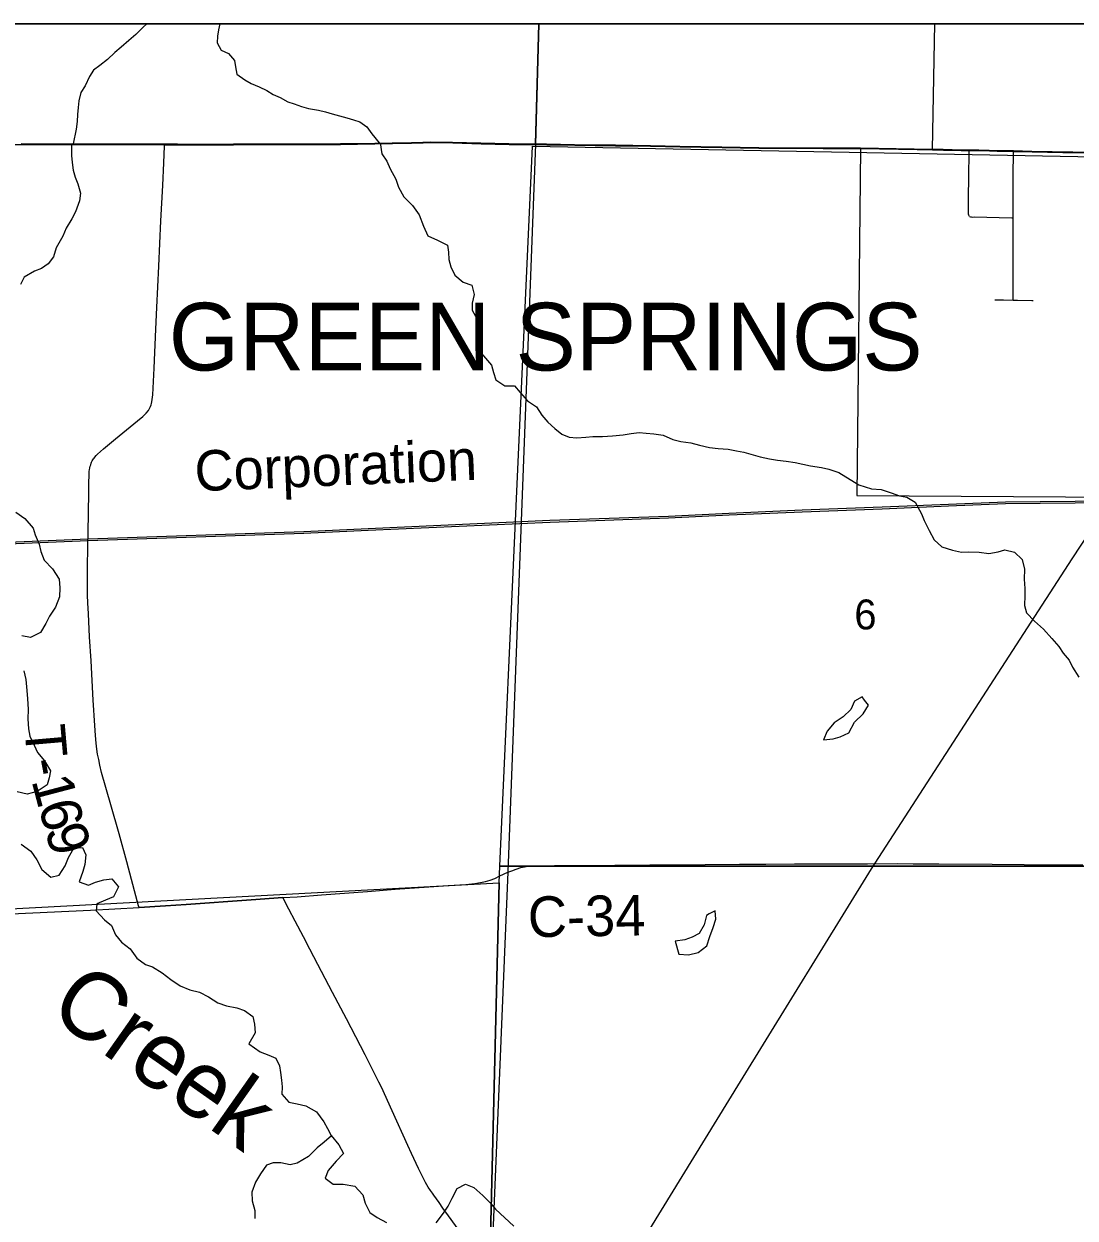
# Model space of a CAD drawing. Extents: x 0 to 34, y 0 to 22.
# Drawn here: x 6.439 to 7.175, y 20.064 to 20.9 of the extents above; entities that cross this region are included whole.
import ezdxf

# ---------------------------------------------------------------- set-up
doc = ezdxf.new("R2010")
doc.units = 0
for name, color, linetype in [('GM_X_City_Street', 7, 'Continuous'), ('GM_X_Corporation', 7, 'Continuous'), ('GM_X_Corporation_Text', 7, 'Continuous'), ('GM_X_County_Road', 7, 'Continuous'), ('GM_X_County_Road_Text', 7, 'Continuous'), ('GM_X_Minor_Lake', 7, 'Continuous'), ('GM_X_Minor_River', 7, 'Continuous'), ('GM_X_Minor_River_Text', 7, 'Continuous'), ('GM_X_Rail_Line', 7, 'Continuous'), ('GM_X_Rail_Line_Text', 7, 'Continuous'), ('GM_X_Section_Text', 7, 'Continuous'), ('GM_X_Township_Road', 7, 'Continuous'), ('GM_X_Township_Road_Text', 7, 'Continuous'), ('SH_Data', 7, 'Continuous')]:
    doc.layers.add(name, color=color, linetype=linetype)

msp = doc.modelspace()

# ---------------------------------------------------------------- linework, layer by layer
at = {"layer": 'GM_X_City_Street'}
for points in [[(7.10112, 20.76525), (7.1008, 20.76573), (7.10065, 20.76622), (7.10053, 20.76682), (7.10052, 20.76744), (7.10042, 20.76931), (7.10045, 20.77259), (7.10041, 20.78121), (7.10059, 20.78997), (7.10077, 20.79874), (7.10083, 20.8043), (7.10087, 20.81065), (7.10088, 20.81138)], [(7.13164, 20.70675), (7.13164, 20.70778), (7.13167, 20.71185), (7.13163, 20.73614), (7.13178, 20.74982), (7.13172, 20.76426), (7.13171, 20.76758), (7.13169, 20.78127), (7.13179, 20.79403), (7.13203, 20.81001), (7.13204, 20.81081)], [(7.10112, 20.76525), (7.1018, 20.76499), (7.10245, 20.7649), (7.10336, 20.76486), (7.10441, 20.7649), (7.13072, 20.76428), (7.13172, 20.76426)], [(7.11889, 20.70698), (7.12482, 20.70688), (7.13164, 20.70675), (7.13473, 20.70669), (7.14467, 20.7065), (7.1456, 20.7065)]]:
    msp.add_lwpolyline(points, dxfattribs=at)
at = {"layer": 'GM_X_Corporation'}
for points in [[(8.9, 20.9), (2.1, 20.9)], [(6.43728, 20.81597), (6.455, 20.81586), (6.49788, 20.8159), (6.51124, 20.8159), (6.53738, 20.81573), (6.54665, 20.81576), (6.55659, 20.81567), (6.58581, 20.81575), (6.60943, 20.81589), (6.6231, 20.81581), (6.64388, 20.81578), (6.66067, 20.81598), (6.67247, 20.81615), (6.69702, 20.81654), (6.7104, 20.81681), (6.7184, 20.81707), (6.72404, 20.81719), (6.73918, 20.81697), (6.75907, 20.81646), (6.77865, 20.816), (6.79733, 20.81582), (6.79968, 20.9), (3.80131, 20.9)], [(8.9, 20.9), (6.79968, 20.9), (6.79733, 20.81582), (6.80505, 20.81575), (6.82462, 20.81548), (6.8532, 20.81506), (6.87775, 20.81462), (6.89835, 20.81423), (6.92778, 20.81367), (6.95357, 20.81337), (6.99856, 20.81315), (7.02492, 20.81305), (7.07501, 20.81217), (7.08275, 20.81203), (7.09521, 20.81169), (7.10077, 20.81165), (7.10763, 20.8116), (7.1149, 20.81141), (7.12034, 20.81127), (7.1296, 20.81114), (7.13193, 20.81108), (7.14484, 20.81082), (7.17346, 20.81025), (7.19996, 20.80975)], [(7.61604, 20.9), (7.07654, 20.9), (7.07501, 20.81217), (7.02492, 20.81305), (7.02214, 20.57001), (7.2781, 20.56846)], [(7.19996, 20.80975), (7.17346, 20.81025), (7.14484, 20.81082), (7.13193, 20.81108), (7.1296, 20.81114), (7.12034, 20.81127), (7.1149, 20.81141), (7.10763, 20.8116), (7.10077, 20.81165), (7.09521, 20.81169), (7.08275, 20.81203), (7.07501, 20.81217), (7.02492, 20.81305), (6.99856, 20.81315), (6.95357, 20.81337), (6.92778, 20.81367), (6.89835, 20.81423), (6.87775, 20.81462), (6.8532, 20.81506), (6.82462, 20.81548), (6.80505, 20.81575), (6.79733, 20.81582), (6.77865, 20.816), (6.75907, 20.81646), (6.73918, 20.81697), (6.72404, 20.81719), (6.7184, 20.81707), (6.7104, 20.81681), (6.69702, 20.81654), (6.67247, 20.81615), (6.66067, 20.81598), (6.64388, 20.81578), (6.6231, 20.81581), (6.60943, 20.81589), (6.58581, 20.81575), (6.55659, 20.81567), (6.54665, 20.81576), (6.53738, 20.81573), (6.51124, 20.8159), (6.49788, 20.8159), (6.455, 20.81586), (6.43728, 20.81597)], [(6.43728, 20.81597), (6.455, 20.81586), (6.49788, 20.8159), (6.51124, 20.8159), (6.53738, 20.81573), (6.54665, 20.81576), (6.55659, 20.81567), (6.58581, 20.81575), (6.60943, 20.81589), (6.6231, 20.81581), (6.64388, 20.81578), (6.66067, 20.81598), (6.67247, 20.81615), (6.69702, 20.81654), (6.7104, 20.81681), (6.7184, 20.81707), (6.72404, 20.81719), (6.73918, 20.81697), (6.75907, 20.81646), (6.77865, 20.816), (6.79733, 20.81582), (6.80505, 20.81575), (6.82462, 20.81548), (6.8532, 20.81506), (6.87775, 20.81462), (6.89835, 20.81423), (6.92778, 20.81367), (6.95357, 20.81337), (6.99856, 20.81315), (7.02492, 20.81305), (7.07501, 20.81217), (7.08275, 20.81203), (7.09521, 20.81169), (7.10077, 20.81165), (7.10763, 20.8116), (7.1149, 20.81141), (7.12034, 20.81127), (7.1296, 20.81114), (7.13193, 20.81108), (7.14484, 20.81082), (7.17346, 20.81025), (7.19996, 20.80975)], [(6.43728, 20.81597), (6.455, 20.81586), (6.49788, 20.8159), (6.51124, 20.8159), (6.53738, 20.81573), (6.54665, 20.81576), (6.55659, 20.81567), (6.58581, 20.81575), (6.60943, 20.81589), (6.6231, 20.81581), (6.64388, 20.81578), (6.66067, 20.81598), (6.67247, 20.81615), (6.69702, 20.81654), (6.7104, 20.81681), (6.7184, 20.81707), (6.72404, 20.81719), (6.73918, 20.81697), (6.75907, 20.81646), (6.77865, 20.816), (6.79733, 20.81582), (6.77787, 20.30669), (6.76561, 20.00895)], [(7.19996, 20.80975), (7.17346, 20.81025), (7.14484, 20.81082), (7.13193, 20.81108), (7.1296, 20.81114), (7.12034, 20.81127), (7.1149, 20.81141), (7.10763, 20.8116), (7.10077, 20.81165), (7.09521, 20.81169), (7.08275, 20.81203), (7.07501, 20.81217), (7.02492, 20.81305), (6.99856, 20.81315), (6.95357, 20.81337), (6.92778, 20.81367), (6.89835, 20.81423), (6.87775, 20.81462), (6.8532, 20.81506), (6.82462, 20.81548), (6.80505, 20.81575), (6.79733, 20.81582), (6.77787, 20.30669), (6.76561, 20.00895)]]:
    msp.add_lwpolyline(points, dxfattribs=at)
for points in [[(6.7951, 20.81454), (7.27539, 20.80543), (7.27412, 20.31079), (6.77234, 20.31066)], [(6.77234, 20.31066), (7.27412, 20.31079), (7.26913, 19.80885), (6.75975, 19.80499), (6.77189, 20.29891)], [(6.25404, 20.2716), (6.77189, 20.29891), (6.75975, 19.80499), (6.75951, 19.79722), (6.2587, 19.76677)]]:
    msp.add_lwpolyline(points, close=True, dxfattribs=at)
at = {"layer": 'GM_X_County_Road'}
for p, q in [((6.79744, 20.81554), (6.7998, 20.9)), ((7.02503, 20.81278), (7.0646, 20.81208)), ((7.0646, 20.81208), (7.07512, 20.81189))]:
    msp.add_line(p, q, dxfattribs=at)
for points in [[(6.29547, 20.81566), (6.30376, 20.81554), (6.33453, 20.81553), (6.35442, 20.81556), (6.39389, 20.81563), (6.43739, 20.81569), (6.45511, 20.81558), (6.49799, 20.81562), (6.51135, 20.81562), (6.53749, 20.81545)], [(6.53749, 20.81545), (6.54676, 20.81548), (6.5567, 20.8154), (6.58592, 20.81547), (6.60954, 20.81562), (6.62321, 20.81553), (6.64399, 20.8155), (6.66078, 20.81571), (6.67258, 20.81587), (6.69713, 20.81627), (6.71051, 20.81653), (6.71852, 20.8168), (6.72415, 20.81691), (6.73929, 20.81669), (6.75918, 20.81618), (6.77876, 20.81572), (6.79744, 20.81554)], [(6.79744, 20.81554), (6.80517, 20.81547), (6.82473, 20.8152), (6.85331, 20.81479), (6.87786, 20.81434), (6.89846, 20.81395), (6.92789, 20.8134), (6.95368, 20.8131), (6.99867, 20.81288), (7.02503, 20.81278)], [(7.07512, 20.81189), (7.08286, 20.81175), (7.09532, 20.81141), (7.10088, 20.81138)], [(7.10088, 20.81138), (7.10774, 20.81133), (7.11501, 20.81113), (7.12045, 20.81099), (7.12971, 20.81087), (7.13204, 20.81081)], [(7.13204, 20.81081), (7.14495, 20.81055), (7.16654, 20.81011)], [(7.16654, 20.81011), (7.17357, 20.80997), (7.20007, 20.80947), (7.21463, 20.80912), (7.22592, 20.80892)], [(6.62038, 20.28865), (6.63048, 20.28928), (6.64752, 20.29065), (6.67976, 20.29296), (6.69898, 20.29448), (6.73619, 20.29709), (6.74859, 20.29794), (6.75475, 20.29855), (6.75872, 20.29915), (6.76232, 20.29996), (6.76556, 20.30095), (6.76873, 20.30215), (6.77239, 20.3038), (6.77798, 20.30641)], [(6.77798, 20.30641), (6.78065, 20.3075), (6.78363, 20.3085), (6.78702, 20.30964), (6.79078, 20.31044), (6.79417, 20.31081), (6.7967, 20.31094), (6.80092, 20.31099), (6.81057, 20.31122), (6.85284, 20.31139), (6.86744, 20.31148), (6.87739, 20.3116), (6.89199, 20.31165), (6.94016, 20.31201), (6.95849, 20.31214), (6.9787, 20.31231), (7.00108, 20.31231), (7.02964, 20.31239), (7.05075, 20.31243), (7.06164, 20.31238), (7.07966, 20.3122), (7.11696, 20.31197), (7.13934, 20.31183), (7.18036, 20.3116)], [(6.51975, 20.28164), (6.53833, 20.28293), (6.5528, 20.28394), (6.59829, 20.2872), (6.62038, 20.28865)], [(6.25408, 20.27027), (6.31869, 20.27283), (6.37801, 20.27524), (6.43018, 20.27742), (6.4857, 20.27993), (6.51975, 20.28164)]]:
    msp.add_lwpolyline(points, dxfattribs=at)
at = {"layer": 'GM_X_Minor_Lake'}
for points in [[(7.02768, 20.42688), (7.02603, 20.42913), (7.02071, 20.42613), (7.01803, 20.42027), (7.0127, 20.41518), (7.00644, 20.41104), (7.00148, 20.40519), (6.9988, 20.39914)], [(6.9988, 20.39914), (7.00562, 20.39986), (7.01054, 20.40116), (7.01661, 20.40397), (7.02063, 20.41134), (7.02671, 20.41737), (7.03034, 20.42323), (7.02768, 20.42688)], [(6.89508, 20.25827), (6.89767, 20.24915), (6.90429, 20.24873), (6.91111, 20.25021), (6.91719, 20.25492), (6.91931, 20.26154), (6.92161, 20.26779), (6.92354, 20.27365), (6.92301, 20.27954), (6.91894, 20.27727)], [(6.91894, 20.27727), (6.91693, 20.27616), (6.91538, 20.26953), (6.91175, 20.26348), (6.90701, 20.26104), (6.90189, 20.25918), (6.89508, 20.25827)]]:
    msp.add_lwpolyline(points, dxfattribs=at)
at = {"layer": 'GM_X_Minor_River'}
for points in [[(6.52522, 20.9), (6.52264, 20.8977), (6.51746, 20.89263), (6.51267, 20.88831), (6.50712, 20.88363), (6.50271, 20.88007), (6.49754, 20.87519), (6.49237, 20.87088), (6.48778, 20.8677), (6.48507, 20.86317), (6.48197, 20.85675), (6.47888, 20.85204), (6.47767, 20.84617), (6.47705, 20.84143), (6.47661, 20.8365), (6.47637, 20.83176), (6.47574, 20.82645), (6.47366, 20.81611)], [(6.57632, 20.9), (6.57534, 20.8958), (6.57472, 20.89144), (6.57448, 20.8867), (6.57727, 20.88155), (6.58236, 20.87921), (6.58648, 20.87443), (6.58718, 20.86986), (6.58827, 20.86492), (6.59372, 20.86087), (6.59824, 20.85836), (6.60391, 20.85602), (6.60919, 20.8533), (6.61371, 20.8506), (6.61842, 20.84846), (6.62389, 20.84536), (6.62823, 20.84399), (6.63353, 20.84222), (6.63844, 20.84084), (6.64525, 20.83963), (6.65036, 20.83844), (6.6549, 20.83706), (6.66, 20.83567), (6.6653, 20.83429), (6.66983, 20.83291), (6.67418, 20.83154), (6.67926, 20.82807), (6.68281, 20.82309), (6.68781, 20.81689)], [(6.47247, 20.81601), (6.47247, 20.8078), (6.47282, 20.80306), (6.47355, 20.79774), (6.47503, 20.7928), (6.47689, 20.78805), (6.47874, 20.78159), (6.47795, 20.7761), (6.47525, 20.76853), (6.47257, 20.76361), (6.46874, 20.757), (6.46625, 20.75152), (6.46165, 20.74339), (6.45972, 20.73695), (6.45609, 20.73205), (6.45134, 20.72885), (6.4466, 20.72698), (6.43938, 20.72267), (6.4367, 20.71775)], [(6.68845, 20.81678), (6.68959, 20.80913), (6.69315, 20.80399), (6.69558, 20.79866), (6.69951, 20.79124), (6.70136, 20.78573), (6.70511, 20.77907), (6.71112, 20.77297), (6.71582, 20.76649), (6.71898, 20.75851), (6.72197, 20.75166), (6.72857, 20.74859), (6.73574, 20.74513), (6.73647, 20.74038), (6.73662, 20.73507), (6.73792, 20.72995), (6.74072, 20.72424), (6.74675, 20.71927), (6.7526, 20.71715), (6.75445, 20.71069), (6.7529, 20.70463), (6.75287, 20.6997), (6.75642, 20.69342), (6.75941, 20.68714), (6.75804, 20.68052), (6.75629, 20.67332), (6.76099, 20.66779), (6.76644, 20.66112), (6.76792, 20.65618), (6.76959, 20.65105), (6.77581, 20.64684), (6.78262, 20.6468), (6.78657, 20.64203), (6.79164, 20.63631), (6.79805, 20.6321), (6.8018, 20.6262), (6.80593, 20.62124), (6.81083, 20.61685), (6.81572, 20.61303), (6.82082, 20.61091), (6.8263, 20.61031), (6.83255, 20.61084), (6.83748, 20.61119), (6.84429, 20.61134), (6.8513, 20.61186), (6.85869, 20.61257), (6.86418, 20.61349), (6.86986, 20.61421), (6.87478, 20.61361), (6.88008, 20.6132), (6.8867, 20.61221), (6.89349, 20.60932), (6.89897, 20.60777), (6.90597, 20.60697), (6.91202, 20.60523), (6.91901, 20.60367), (6.92525, 20.60287), (6.93225, 20.60245), (6.93792, 20.60127), (6.94302, 20.60029), (6.94794, 20.59893), (6.95455, 20.597), (6.96116, 20.59563), (6.96665, 20.59483), (6.9727, 20.59404), (6.97913, 20.59305), (6.98442, 20.59188), (6.9899, 20.59071), (6.99747, 20.58971), (7.00257, 20.58835), (7.00975, 20.58603), (7.0236, 20.57751)], [(7.0236, 20.57751), (7.03255, 20.57473), (7.03936, 20.57413), (7.04634, 20.572), (7.05219, 20.56988), (7.0573, 20.5689), (7.06314, 20.56526), (7.06763, 20.55727), (7.06931, 20.55252), (7.07286, 20.54549), (7.07642, 20.53902), (7.08169, 20.53406), (7.08924, 20.53174), (7.09547, 20.53037), (7.10077, 20.53072), (7.10796, 20.5303), (7.11457, 20.52951), (7.1212, 20.53061), (7.12594, 20.5319), (7.13274, 20.53035), (7.13801, 20.5252), (7.13967, 20.51855), (7.13944, 20.51154), (7.13978, 20.5049), (7.13994, 20.50015), (7.13971, 20.49295), (7.141, 20.48801), (7.14664, 20.4821), (7.15286, 20.47657), (7.15887, 20.46989), (7.16357, 20.46437), (7.16676, 20.45961), (7.17089, 20.45484), (7.17313, 20.4499), (7.17763, 20.44286)], [(6.43335, 20.55841), (6.43976, 20.55383), (6.44558, 20.54716), (6.44688, 20.54241), (6.44987, 20.53595), (6.45097, 20.53082), (6.45321, 20.52474), (6.45923, 20.51864), (6.46372, 20.51141), (6.46426, 20.50552), (6.46403, 20.49908), (6.46134, 20.49189), (6.45695, 20.48565), (6.45446, 20.48055), (6.45083, 20.47412), (6.44362, 20.47075), (6.43758, 20.47173)], [(6.43895, 20.44726), (6.44043, 20.44118), (6.44096, 20.43606), (6.44168, 20.42809), (6.4422, 20.42031), (6.44178, 20.41387), (6.44231, 20.40666), (6.44322, 20.40153), (6.44621, 20.39526), (6.44864, 20.39031), (6.45353, 20.38441), (6.45765, 20.37737), (6.45686, 20.37244), (6.45532, 20.36752), (6.4483, 20.36282), (6.44129, 20.36115), (6.43449, 20.36271)], [(6.4373, 20.32609), (6.44389, 20.32112), (6.44821, 20.31503), (6.45176, 20.30837), (6.45797, 20.30303), (6.46385, 20.30432), (6.46805, 20.31094), (6.47035, 20.3168), (6.47417, 20.32323), (6.48004, 20.32377), (6.48247, 20.31863), (6.48167, 20.31181), (6.48032, 20.30689), (6.47782, 20.29969), (6.48443, 20.29738), (6.48917, 20.29944), (6.49504, 20.30111), (6.50072, 20.30184), (6.50542, 20.29613), (6.50178, 20.28932), (6.49628, 20.28688), (6.49021, 20.28426), (6.48962, 20.27934), (6.49564, 20.27323), (6.50053, 20.26923), (6.50314, 20.26257), (6.50746, 20.25743), (6.51349, 20.25284), (6.51818, 20.24637), (6.52421, 20.24197), (6.52912, 20.24024), (6.5359, 20.23603), (6.54193, 20.23145), (6.54852, 20.22686), (6.55532, 20.22416), (6.56212, 20.22242), (6.56834, 20.21916), (6.57494, 20.21514), (6.58098, 20.21302), (6.58816, 20.21165), (6.59345, 20.20973), (6.59948, 20.20552), (6.60058, 20.20021), (6.60111, 20.19413), (6.59653, 20.18638), (6.60444, 20.18084), (6.61067, 20.17853), (6.61558, 20.17642), (6.618, 20.17109)], [(6.618, 20.17109), (6.61873, 20.16635), (6.61946, 20.16103), (6.61981, 20.15629), (6.61959, 20.15117), (6.62448, 20.14546), (6.63052, 20.14428), (6.63638, 20.14292), (6.64392, 20.13871), (6.64899, 20.13185), (6.65161, 20.1271), (6.65423, 20.12215), (6.65968, 20.11567), (6.66286, 20.10959), (6.65772, 20.10431), (6.6522, 20.0977), (6.65008, 20.0924), (6.65573, 20.0882), (6.66254, 20.08816), (6.67086, 20.08679), (6.67631, 20.08069), (6.67798, 20.07499), (6.68135, 20.06833), (6.68643, 20.06489), (6.69303, 20.06125)], [(6.65437, 20.12198), (6.64928, 20.11763), (6.64434, 20.11368), (6.63825, 20.10764), (6.63047, 20.10294), (6.62555, 20.10164), (6.61893, 20.10301), (6.61364, 20.10304), (6.6089, 20.10155), (6.6047, 20.0955), (6.60126, 20.08964), (6.59876, 20.08264), (6.59892, 20.07657), (6.60077, 20.06974), (6.60073, 20.06405)], [(6.72784, 20.06105), (6.7328, 20.06785), (6.73604, 20.07276), (6.73891, 20.07844), (6.74236, 20.08505), (6.74824, 20.08825), (6.75409, 20.08575), (6.76049, 20.08021), (6.76538, 20.07544), (6.76932, 20.07068), (6.78212, 20.05885)]]:
    msp.add_lwpolyline(points, dxfattribs=at)
at = {"layer": 'GM_X_Rail_Line'}
for points in [[(4.83086, 16.81428), (4.95348, 17.00356), (5.121, 17.25544), (5.31678, 17.55326), (5.45252, 17.7592), (5.58679, 17.98275), (5.74825, 18.23979), (5.90418, 18.49744), (6.02127, 18.68264), (6.13663, 18.87252), (6.2288, 19.01731), (6.34315, 19.20099), (6.38785, 19.27035), (6.55501, 19.53303), (6.71382, 19.79395), (6.76349, 19.87076), (6.84474, 20.00352), (6.94083, 20.16003), (7.03262, 20.3087), (7.17305, 20.5257), (7.19919, 20.56539)], [(6.26535, 20.53071), (6.48407, 20.5397), (6.63504, 20.54492), (6.68014, 20.54698), (6.80739, 20.55272), (6.89038, 20.55561), (6.93271, 20.55766), (6.98399, 20.55992), (7.03989, 20.56198), (7.08643, 20.56393), (7.12632, 20.56558), (7.1993, 20.56635), (7.30727, 20.56381), (7.45258, 20.56138), (7.51394, 20.56039)], [(6.2654, 20.52947), (6.48412, 20.53846), (6.63509, 20.54368), (6.6802, 20.54573), (6.80744, 20.55148), (6.89043, 20.55437), (6.93276, 20.55642), (6.98404, 20.55868), (7.03994, 20.56074), (7.08648, 20.56269), (7.12635, 20.56433), (7.1993, 20.56511)]]:
    msp.add_lwpolyline(points, dxfattribs=at)
at = {"layer": 'GM_X_Township_Road'}
for points in [[(6.51975, 20.28164), (6.51938, 20.28301), (6.5166, 20.29348), (6.51121, 20.31377), (6.50574, 20.33321), (6.49994, 20.35353), (6.49353, 20.37626), (6.49227, 20.38139), (6.49148, 20.38532), (6.49074, 20.38902), (6.49024, 20.39264), (6.48969, 20.3967), (6.48917, 20.40201), (6.48869, 20.40909), (6.48762, 20.42677), (6.48617, 20.45438), (6.48514, 20.47113), (6.48423, 20.48726), (6.4838, 20.49503), (6.48369, 20.5003), (6.48364, 20.50334), (6.48361, 20.50683), (6.48368, 20.52019), (6.48388, 20.5336), (6.48405, 20.54532), (6.48426, 20.55681), (6.48461, 20.57327), (6.48466, 20.57855), (6.48473, 20.58446), (6.48475, 20.58525), (6.48483, 20.58622), (6.48491, 20.58702), (6.48503, 20.58787), (6.4853, 20.58936), (6.48559, 20.59061), (6.48588, 20.59159), (6.48623, 20.59261), (6.48647, 20.59323), (6.48674, 20.59385), (6.48697, 20.59432), (6.48739, 20.59501), (6.48779, 20.59564), (6.48822, 20.59626), (6.48867, 20.59683), (6.48974, 20.59802), (6.49069, 20.59897), (6.49483, 20.60275), (6.50324, 20.60962), (6.51866, 20.62219), (6.52246, 20.62541), (6.52466, 20.62759), (6.52624, 20.62951), (6.52688, 20.63046), (6.52736, 20.63138), (6.52775, 20.63221), (6.52819, 20.63338), (6.52852, 20.63441), (6.52874, 20.63549), (6.52933, 20.64042), (6.53026, 20.65904), (6.53153, 20.68636), (6.53221, 20.70157), (6.53358, 20.73044), (6.53507, 20.7621), (6.53637, 20.78693), (6.53707, 20.80276), (6.53746, 20.81445), (6.53749, 20.81545)], [(6.62038, 20.28865), (6.59829, 20.2872), (6.5528, 20.28394), (6.53833, 20.28293), (6.51975, 20.28164)], [(6.73627, 20.06613), (6.73243, 20.07142), (6.72974, 20.07527), (6.72621, 20.08037), (6.72509, 20.08189), (6.72386, 20.0837), (6.72225, 20.08613), (6.72122, 20.08781), (6.72028, 20.08933), (6.71929, 20.09122), (6.71834, 20.09312), (6.71529, 20.09923), (6.71042, 20.10967), (6.70787, 20.11533), (6.69698, 20.1394), (6.69148, 20.15142), (6.68959, 20.15561), (6.6877, 20.15956), (6.68459, 20.16572), (6.67802, 20.17875), (6.66494, 20.20382), (6.65518, 20.22229), (6.64483, 20.24188), (6.63931, 20.25257), (6.63482, 20.26125), (6.629, 20.27224), (6.6246, 20.28054), (6.62038, 20.28865)], [(6.76498, 20.01479), (6.76489, 20.01536), (6.76462, 20.01664), (6.76429, 20.01806), (6.76372, 20.02022), (6.76302, 20.02249), (6.7622, 20.0249), (6.76134, 20.02713), (6.76039, 20.02935), (6.75939, 20.03168), (6.75842, 20.03358), (6.75705, 20.03609), (6.75575, 20.0385), (6.75466, 20.04035), (6.75298, 20.04312), (6.75106, 20.04577), (6.73627, 20.06613)]]:
    msp.add_lwpolyline(points, dxfattribs=at)
at = {"layer": 'SH_Data'}
msp.add_line((2.1, 20.9), (8.9, 20.9), dxfattribs=at)

# ---------------------------------------------------------------- texts
at = {"layer": 'GM_X_Corporation_Text'}
msp.add_text('GREEN SPRINGS', height=0.0473485, rotation=0.00001, dxfattribs=at).set_placement((6.54054, 20.65751))
at = {"layer": 'GM_X_County_Road_Text'}
msp.add_text('C-34', height=0.028409, rotation=0.93179, dxfattribs=at).set_placement((6.7921, 20.26093))
at = {"layer": 'GM_X_Minor_River_Text'}
msp.add_text('Creek', height=0.047374, rotation=324.8656, dxfattribs=at).set_placement((6.4549, 20.20713))
at = {"layer": 'GM_X_Rail_Line_Text'}
msp.add_text('Corporation', height=0.0283144, rotation=2.34633, dxfattribs=at).set_placement((6.55912, 20.57293))
at = {"layer": 'GM_X_Section_Text'}
msp.add_text('6', height=0.02093, rotation=0.00001, dxfattribs=at).set_placement((7.02048, 20.47633))
at = {"layer": 'GM_X_Township_Road_Text'}
for s, rotation, p in [('T', 274.92167, (6.43936, 20.40855)), ('-', 280.82586, (6.44162, 20.38422)), ('1', 284.77015, (6.44429, 20.37068)), ('6', 285.72983, (6.44889, 20.35326)), ('9', 285.85863, (6.45365, 20.33635))]:
    msp.add_text(s, height=0.02841, rotation=rotation, dxfattribs=at).set_placement(p)

doc.saveas('drawing.dxf')
